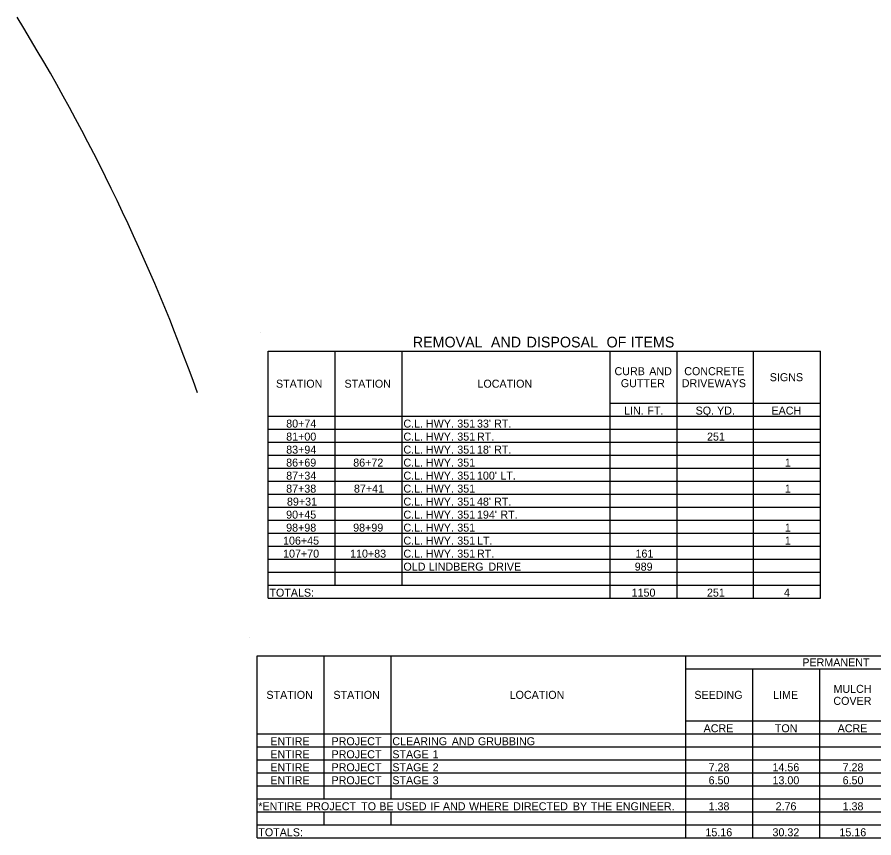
# Model space of a CAD drawing. Extents: x 1197542 to 1207068, y 230488 to 237324.
# Drawn here: x 1199664 to 1200306, y 232374 to 232989 of the extents above; entities that cross this region are included whole.
import ezdxf

# ---------------------------------------------------------------- set-up
doc = ezdxf.new("R2010")
doc.units = 0
doc.layers.add('Default', color=7, linetype='Continuous')
doc.layers.add('R_Proposed Road_Shoulder', color=7, linetype='Continuous')

msp = doc.modelspace()

# ---------------------------------------------------------------- linework, layer by layer
at = {"layer": 'Default'}
for p, q in [((1199846.68, 232752.26), (1199846.68, 232752.26)), ((1199852.53, 232738.61), (1200266.41, 232738.61)), ((1199852.53, 232553.36), (1199852.53, 232738.61)), ((1199852.53, 232553.36), (1199852.53, 232738.61)), ((1199902.74, 232563.11), (1199902.74, 232738.61)), ((1199952.95, 232563.11), (1199952.95, 232738.61)), ((1200108.95, 232553.36), (1200108.95, 232738.61)), ((1200159.16, 232553.36), (1200159.16, 232738.61)), ((1200216.2, 232553.36), (1200216.2, 232738.61)), ((1200266.41, 232553.36), (1200266.41, 232738.61)), ((1200266.41, 232553.36), (1200266.41, 232738.61)), ((1200108.95, 232699.61), (1200266.41, 232699.61)), ((1199852.53, 232689.86), (1200266.41, 232689.86)), ((1199902.74, 232563.11), (1199902.74, 232689.86)), ((1199952.95, 232563.11), (1199952.95, 232689.86)), ((1200108.95, 232553.36), (1200108.95, 232689.86)), ((1200159.16, 232553.36), (1200159.16, 232689.86)), ((1200216.2, 232553.36), (1200216.2, 232689.86)), ((1199852.53, 232680.11), (1200266.41, 232680.11)), ((1199852.53, 232670.36), (1200266.41, 232670.36)), ((1199852.53, 232660.61), (1200266.41, 232660.61)), ((1199852.53, 232650.86), (1200266.41, 232650.86)), ((1199852.53, 232641.11), (1200266.41, 232641.11)), ((1199852.53, 232631.36), (1200266.41, 232631.36)), ((1199852.53, 232621.61), (1200266.41, 232621.61)), ((1199852.53, 232611.86), (1200266.41, 232611.86)), ((1199852.53, 232602.11), (1200266.41, 232602.11)), ((1199852.53, 232592.36), (1200266.41, 232592.36)), ((1199852.53, 232582.61), (1200266.41, 232582.61)), ((1199852.53, 232572.86), (1200266.41, 232572.86)), ((1199852.53, 232563.11), (1200266.41, 232563.11)), ((1200216.2, 232563.11), (1200266.41, 232563.11)), ((1199852.53, 232553.36), (1200266.41, 232553.36)), ((1199838.37, 232523.81), (1199838.37, 232523.81)), ((1199844.22, 232510.16), (1201056.63, 232510.16)), ((1199844.22, 232373.66), (1199844.22, 232510.16)), ((1199844.22, 232373.66), (1199844.22, 232510.16)), ((1199894.43, 232402.91), (1199894.43, 232510.16)), ((1199944.64, 232402.91), (1199944.64, 232510.16)), ((1200165.48, 232373.66), (1200165.48, 232510.16)), ((1200165.48, 232500.41), (1201056.63, 232500.41)), ((1200215.69, 232373.66), (1200215.69, 232500.41)), ((1200265.9, 232373.66), (1200265.9, 232500.41)), ((1200165.48, 232461.41), (1201056.63, 232461.41)), ((1200215.69, 232373.66), (1200215.69, 232461.41)), ((1200265.9, 232383.41), (1200265.9, 232461.41)), ((1199844.22, 232451.66), (1201056.63, 232451.66)), ((1199894.43, 232402.91), (1199894.43, 232451.66)), ((1199944.64, 232402.91), (1199944.64, 232451.66)), ((1200165.48, 232402.91), (1200165.48, 232451.66)), ((1199844.22, 232441.91), (1201056.63, 232441.91)), ((1199844.22, 232432.16), (1201056.63, 232432.16)), ((1199844.22, 232422.41), (1201056.63, 232422.41)), ((1199844.22, 232412.66), (1201056.63, 232412.66)), ((1199844.22, 232402.91), (1201056.63, 232402.91)), ((1199844.22, 232393.16), (1201056.63, 232393.16)), ((1199894.43, 232383.41), (1199894.43, 232393.16)), ((1199894.43, 232383.41), (1199894.43, 232393.16)), ((1199944.64, 232383.41), (1199944.64, 232393.16)), ((1199944.64, 232383.41), (1199944.64, 232393.16)), ((1200165.48, 232373.66), (1200165.48, 232393.16)), ((1199844.22, 232383.41), (1201056.63, 232383.41)), ((1200215.69, 232383.41), (1200426.78, 232383.41)), ((1199844.22, 232373.66), (1201056.63, 232373.66))]:
    msp.add_line(p, q, dxfattribs=at)
at = {"layer": 'R_Proposed Road_Shoulder'}
msp.add_arc((1198361.87, 232190.51), 1527.89, 19.77327, 31.5123, dxfattribs=at)

# ---------------------------------------------------------------- texts
at = {"layer": 'Default'}
for s, height, p in [('REMOVAL', 8, (1199960.94, 232741.43)), (' AND', 8, (1200016.5, 232741.43)), (' DISPOSAL', 8, (1200043.27, 232741.43)), (' OF', 8, (1200103.18, 232741.43)), (' ITEMS', 8, (1200121.29, 232741.43)), ('CURB', 6, (1200112.12, 232720.61)), (' AND', 6, (1200135.92, 232720.61)), ('CONCRETE', 6, (1200164.37, 232720.61)), ('SIGNS', 6, (1200228.47, 232716.11)), ('STATION', 6, (1199858.41, 232711.23)), ('STATION', 6, (1199909.78, 232711.23)), ('LOCATION', 6, (1200009.4, 232711.23)), ('GUTTER', 6, (1200116.84, 232711.61)), ('DRIVEWAYS', 6, (1200162.5, 232711.61)), ('LIN.', 6, (1200119.27, 232691.06)), (' FT.', 6, (1200134.52, 232691.06)), ('SQ.', 6, (1200172.89, 232691.06)), (' YD.', 6, (1200186.75, 232691.06)), ('EACH', 6, (1200229.75, 232691.06)), ('80+74', 6, (1199866.07, 232681.31)), ('C.L.', 6, (1199953.93, 232681.31)), (' HWY.', 6, (1199968.57, 232681.31)), (' 351', 6, (1199992.05, 232681.31)), (" 33'", 6, (1200006.82, 232681.31)), (' RT.', 6, (1200019.67, 232681.31)), ('81+00', 6, (1199866.07, 232671.56)), ('C.L.', 6, (1199953.93, 232671.56)), (' HWY.', 6, (1199968.57, 232671.56)), (' 351', 6, (1199992.05, 232671.56)), (' RT.', 6, (1200006.82, 232671.56)), ('251', 6, (1200181.46, 232671.56)), ('83+94', 6, (1199866.07, 232661.81)), ('C.L.', 6, (1199953.93, 232661.81)), (' HWY.', 6, (1199968.57, 232661.81)), (' 351', 6, (1199992.05, 232661.81)), (" 18'", 6, (1200006.82, 232661.81)), (' RT.', 6, (1200019.67, 232661.81)), ('86+69', 6, (1199866.05, 232652.06)), ('86+72', 6, (1199916.3, 232652.06)), ('C.L.', 6, (1199953.93, 232652.06)), (' HWY.', 6, (1199968.57, 232652.06)), (' 351', 6, (1199992.05, 232652.06)), ('1', 6, (1200239.75, 232652.06)), ('87+34', 6, (1199866.07, 232642.31)), ('C.L.', 6, (1199953.93, 232642.31)), (' HWY.', 6, (1199968.57, 232642.31)), (' 351', 6, (1199992.05, 232642.31)), (" 100'", 6, (1200006.82, 232642.31)), (' LT.', 6, (1200024.33, 232642.31)), ('87+38', 6, (1199866.05, 232632.56)), ('87+41', 6, (1199916.85, 232632.56)), ('C.L.', 6, (1199953.93, 232632.56)), (' HWY.', 6, (1199968.57, 232632.56)), (' 351', 6, (1199992.05, 232632.56)), ('1', 6, (1200239.75, 232632.56)), ('89+31', 6, (1199866.64, 232622.81)), ('C.L.', 6, (1199953.93, 232622.81)), (' HWY.', 6, (1199968.57, 232622.81)), (' 351', 6, (1199992.05, 232622.81)), (" 48'", 6, (1200006.82, 232622.81)), (' RT.', 6, (1200019.67, 232622.81)), ('90+45', 6, (1199866.03, 232613.06)), ('C.L.', 6, (1199953.93, 232613.06)), (' HWY.', 6, (1199968.57, 232613.06)), (' 351', 6, (1199992.05, 232613.06)), (" 194'", 6, (1200006.82, 232613.06)), (' RT.', 6, (1200024.33, 232613.06)), ('98+98', 6, (1199866.05, 232603.31)), ('98+99', 6, (1199916.26, 232603.31)), ('C.L.', 6, (1199953.93, 232603.31)), (' HWY.', 6, (1199968.57, 232603.31)), (' 351', 6, (1199992.05, 232603.31)), ('1', 6, (1200239.75, 232603.31)), ('106+45', 6, (1199863.7, 232593.56)), ('C.L.', 6, (1199953.93, 232593.56)), (' HWY.', 6, (1199968.57, 232593.56)), (' 351', 6, (1199992.05, 232593.56)), (' LT.', 6, (1200006.82, 232593.56)), ('1', 6, (1200239.75, 232593.56)), ('107+70', 6, (1199863.74, 232583.81)), ('110+83', 6, (1199913.94, 232583.81)), ('C.L.', 6, (1199953.93, 232583.81)), (' 351', 6, (1199992.05, 232583.81)), ('161', 6, (1200127.84, 232583.81)), (' HWY.', 6, (1199968.57, 232583.81)), (' RT.', 6, (1200006.82, 232583.81)), ('OLD', 6, (1199953.93, 232574.06)), (' LINDBERG', 6, (1199970.71, 232574.06)), (' DRIVE', 6, (1200015.38, 232574.06)), ('989', 6, (1200127.25, 232574.06)), ('TOTALS:', 6, (1199853.5, 232554.56)), ('1150', 6, (1200124.94, 232554.56)), ('251', 6, (1200181.37, 232554.56)), ('4', 6, (1200239.07, 232554.56)), ('PERMANENT', 6, (1200252.85, 232502.29)), ('MULCH', 6, (1200276.2, 232482.41)), ('STATION', 6, (1199851.26, 232477.91)), ('STATION', 6, (1199901.47, 232477.91)), ('LOCATION', 6, (1200033.51, 232477.91)), ('SEEDING', 6, (1200171.97, 232477.91)), ('LIME', 6, (1200230.99, 232477.91)), ('COVER', 6, (1200276.12, 232473.41)), ('ACRE', 6, (1200178.91, 232452.86)), ('TON', 6, (1200232.28, 232452.86)), ('ACRE', 6, (1200279.34, 232452.86)), ('ENTIRE', 6, (1199854.17, 232443.11)), ('PROJECT', 6, (1199900.05, 232443.11)), ('CLEARING', 6, (1199945.62, 232443.11)), (' AND', 6, (1199987.95, 232443.11)), (' GRUBBING', 6, (1200007.53, 232443.11)), ('ENTIRE', 6, (1199854.17, 232433.36)), ('PROJECT', 6, (1199900.05, 232433.36)), ('STAGE', 6, (1199945.62, 232433.36)), (' 1', 6, (1199973.59, 232433.36)), ('ENTIRE', 6, (1199854.17, 232423.61)), ('PROJECT', 6, (1199900.05, 232423.61)), ('STAGE', 6, (1199945.62, 232423.61)), (' 2', 6, (1199973.59, 232423.61)), ('7.28', 6, (1200182.62, 232423.61)), ('14.56', 6, (1200230.5, 232423.61)), ('7.28', 6, (1200283.04, 232423.61)), ('ENTIRE', 6, (1199854.17, 232413.86)), ('PROJECT', 6, (1199900.05, 232413.86)), ('STAGE', 6, (1199945.62, 232413.86)), (' 3', 6, (1199973.59, 232413.86)), ('6.50', 6, (1200182.63, 232413.86)), ('13.00', 6, (1200230.51, 232413.86)), ('6.50', 6, (1200283.06, 232413.86)), ('*ENTIRE', 6, (1199845.19, 232394.36)), (' PROJECT', 6, (1199878.75, 232394.36)), (' TO', 6, (1199920.04, 232394.36)), (' BE', 6, (1199933.64, 232394.36)), (' USED', 6, (1199946.7, 232394.36)), (' IF', 6, (1199971.88, 232394.36)), (' AND', 6, (1199981.27, 232394.36)), (' WHERE', 6, (1200000.85, 232394.36)), (' DIRECTED', 6, (1200033.94, 232394.36)), (' BY', 6, (1200078.67, 232394.36)), (' THE', 6, (1200092.12, 232394.36)), (' ENGINEER.', 6, (1200110.77, 232394.36)), ('1.38', 6, (1200182.62, 232394.36)), ('2.76', 6, (1200232.83, 232394.36)), ('1.38', 6, (1200283.04, 232394.36)), ('TOTALS:', 6, (1199845.19, 232374.86)), ('15.16', 6, (1200180.25, 232374.86)), ('30.32', 6, (1200230.52, 232374.86)), ('15.16', 6, (1200280.67, 232374.86))]:
    msp.add_text(s, height=height, dxfattribs=at).set_placement(p)

doc.saveas('drawing.dxf')
